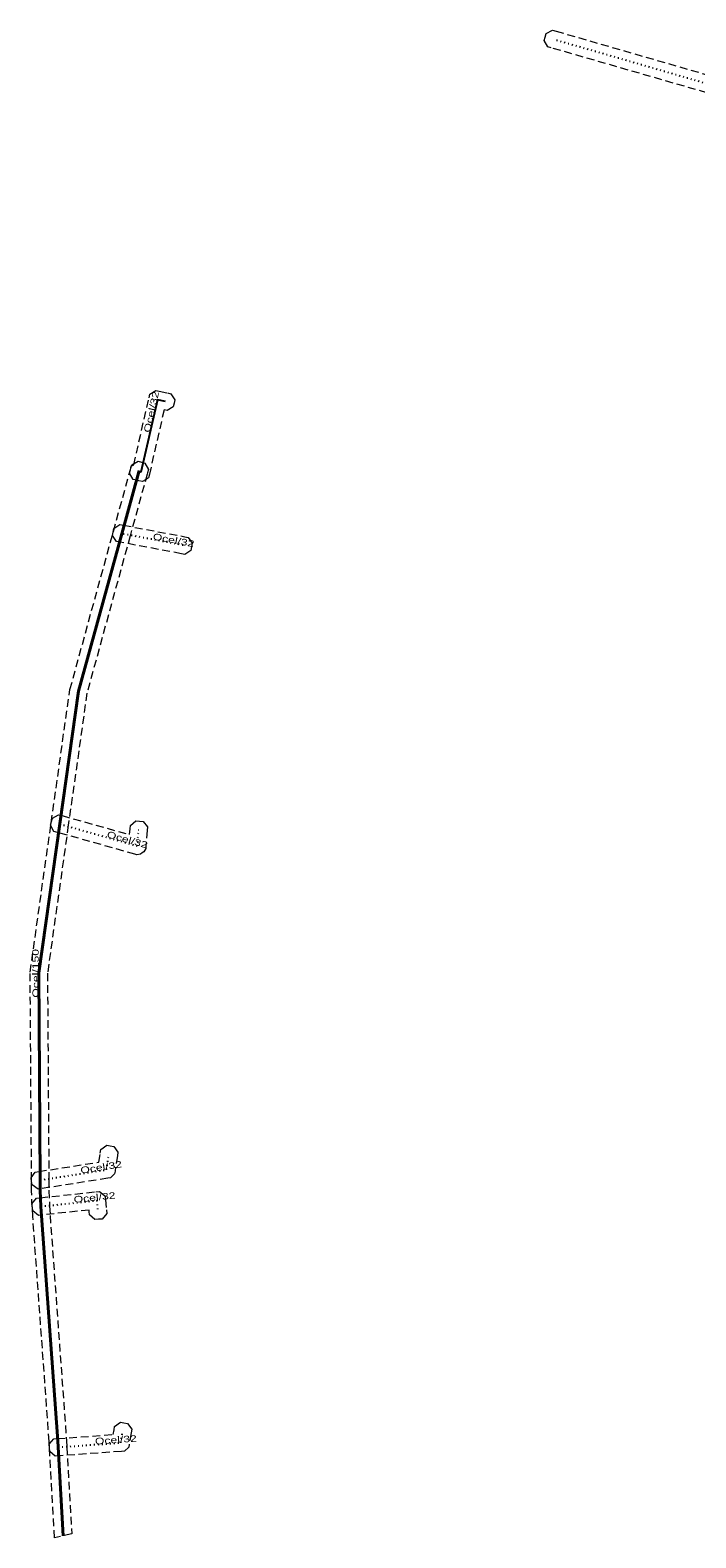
# Model space of a CAD drawing. Extents: x -583333 to -583115, y -1209681 to -1209498.
# Drawn here: x -583332.7 to -583255.9, y -1209681.3 to -1209507.4 of the extents above; entities that cross this region are included whole.
import ezdxf

# ---------------------------------------------------------------- set-up
doc = ezdxf.new("R2010")
doc.units = 0
doc.header["$LTSCALE"] = 0.3
doc.linetypes.add('DOTTED', pattern=[1.5, 0.3, -1.2])
doc.linetypes.add('MEDIUM_DASHED', pattern=[4.5, 3, -1.5])
for name, color, linetype, lineweight in [('1', 7, 'MEDIUM_DASHED', 13), ('14', 7, 'Continuous', 40), ('18', 7, 'DOTTED', 25)]:
    doc.layers.add(name, color=color, linetype=linetype, lineweight=lineweight)
doc.layers.add('20', color=7, linetype='Continuous')

msp = doc.modelspace()

# ---------------------------------------------------------------- linework, layer by layer
at = {"layer": '1'}
for points in [[(-583232.408, -1209539.651), (-583232.555, -1209539.264), (-583240.332, -1209518.712), (-583272.551, -1209509.395), (-583272.949, -1209509.28), (-583273.349, -1209508.554), (-583273.234, -1209508.156), (-583273.119, -1209507.758), (-583272.393, -1209507.358), (-583271.995, -1209507.473), (-583239.296, -1209516.929), (-583239.069, -1209516.995), (-583238.723, -1209517.315), (-583238.639, -1209517.536), (-583230.685, -1209538.556), (-583230.538, -1209538.943), (-583230.879, -1209539.698), (-583231.266, -1209539.845), (-583231.653, -1209539.992)], [(-583321.005, -1209557.674), (-583320.705, -1209557.49), (-583318.945, -1209549.768), (-583318.854, -1209549.368), (-583318.161, -1209548.926), (-583317.76, -1209549.012), (-583316.83, -1209549.212), (-583316.425, -1209549.299), (-583315.975, -1209549.995), (-583316.062, -1209550.4), (-583316.149, -1209550.805), (-583316.845, -1209551.255), (-583317.215, -1209551.176), (-583318.905, -1209558.592), (-583318.998, -1209558.999), (-583319.353, -1209559.22), (-583319.707, -1209559.44), (-583320.113, -1209559.342), (-583320.363, -1209559.282), (-583320.766, -1209559.185), (-583321.199, -1209558.48), (-583321.102, -1209558.077)], [(-583327.861, -1209680.815), (-583329.837, -1209681.295), (-583330.428, -1209670.896), (-583330.468, -1209670.174), (-583332.358, -1209644.209), (-583332.409, -1209643.107), (-583332.5, -1209641.244), (-583332.5, -1209640.023), (-583332.66, -1209616.033), (-583330.24, -1209598.801), (-583328.071, -1209583.427), (-583323.054, -1209565.185), (-583321.093, -1209558.04), (-583321.052, -1209557.895), (-583320.938, -1209557.497), (-583320.213, -1209557.095), (-583319.815, -1209557.208), (-583319.417, -1209557.322), (-583319.015, -1209558.047), (-583319.128, -1209558.445), (-583319.167, -1209558.58), (-583321.126, -1209565.715), (-583326.109, -1209583.833), (-583328.26, -1209599.079), (-583330.66, -1209616.167), (-583330.5, -1209640.017), (-583330.5, -1209641.196), (-583330.411, -1209643.013), (-583330.362, -1209644.091), (-583328.472, -1209670.046), (-583328.432, -1209670.784)], [(-583314.798, -1209567.84), (-583315.205, -1209567.763), (-583322.275, -1209566.433), (-583322.682, -1209566.356), (-583323.15, -1209565.672), (-583323.073, -1209565.265), (-583322.996, -1209564.858), (-583322.312, -1209564.39), (-583321.905, -1209564.467), (-583314.835, -1209565.797), (-583314.428, -1209565.874), (-583313.96, -1209566.558), (-583314.037, -1209566.965), (-583314.114, -1209567.372)], [(-583329.378, -1209597.865), (-583328.979, -1209597.977), (-583321.193, -1209600.17), (-583321.136, -1209599.514), (-583321.101, -1209599.101), (-583320.467, -1209598.568), (-583320.054, -1209598.604), (-583319.641, -1209598.639), (-583319.108, -1209599.273), (-583319.144, -1209599.686), (-583319.304, -1209601.546), (-583319.323, -1209601.769), (-583319.547, -1209602.155), (-583319.731, -1209602.282), (-583319.915, -1209602.409), (-583320.356, -1209602.483), (-583320.571, -1209602.423), (-583329.521, -1209599.903), (-583329.92, -1209599.791), (-583330.325, -1209599.068), (-583330.213, -1209598.669), (-583330.101, -1209598.27)], [(-583332.064, -1209639.096), (-583331.655, -1209639.032), (-583324.733, -1209637.945), (-583324.568, -1209636.903), (-583324.503, -1209636.494), (-583323.832, -1209636.007), (-583323.423, -1209636.072), (-583323.014, -1209636.137), (-583322.527, -1209636.808), (-583322.592, -1209637.217), (-583322.872, -1209638.977), (-583322.923, -1209639.298), (-583323.384, -1209639.757), (-583323.705, -1209639.808), (-583331.345, -1209641.008), (-583331.754, -1209641.072), (-583332.424, -1209640.584), (-583332.488, -1209640.175), (-583332.552, -1209639.766)], [(-583331.928, -1209642.11), (-583331.516, -1209642.066), (-583325.066, -1209641.376), (-583324.648, -1209641.331), (-583324.324, -1209641.599), (-583323.999, -1209641.866), (-583323.964, -1209642.286), (-583323.864, -1209643.466), (-583323.829, -1209643.879), (-583324.363, -1209644.511), (-583324.776, -1209644.546), (-583325.189, -1209644.581), (-583325.821, -1209644.047), (-583325.856, -1209643.634), (-583325.87, -1209643.473), (-583331.304, -1209644.054), (-583331.716, -1209644.098), (-583332.36, -1209643.578), (-583332.404, -1209643.166), (-583332.448, -1209642.754)], [(-583329.915, -1209669.872), (-583329.502, -1209669.843), (-583323.072, -1209669.379), (-583322.987, -1209668.852), (-583322.922, -1209668.443), (-583322.251, -1209667.957), (-583321.842, -1209668.023), (-583321.433, -1209668.088), (-583320.947, -1209668.759), (-583321.013, -1209669.168), (-583321.223, -1209670.478), (-583321.278, -1209670.822), (-583321.791, -1209671.292), (-583322.138, -1209671.317), (-583329.358, -1209671.837), (-583329.771, -1209671.867), (-583330.398, -1209671.325), (-583330.427, -1209670.912), (-583330.457, -1209670.499)]]:
    msp.add_lwpolyline(points, close=True, dxfattribs=at)
at = {"layer": '14', "lineweight": 25}
msp.add_lwpolyline([(-583317.04, -1209550.19), (-583317.97, -1209549.99), (-583319.88, -1209558.37), (-583320.13, -1209558.31)], dxfattribs=at)
at = {"layer": '14'}
msp.add_lwpolyline([(-583328.849, -1209681.055), (-583329.43, -1209670.84), (-583329.47, -1209670.11), (-583331.36, -1209644.15), (-583331.41, -1209643.06), (-583331.5, -1209641.22), (-583331.5, -1209640.02), (-583331.66, -1209616.1), (-583329.25, -1209598.94), (-583327.09, -1209583.63), (-583322.09, -1209565.45), (-583320.13, -1209558.31), (-583320.09, -1209558.17)], dxfattribs=at)
at = {"layer": '18'}
msp.add_line((-583315.02, -1209566.78), (-583322.09, -1209565.45), dxfattribs=at)
for points in [[(-583231.62, -1209538.91), (-583239.574, -1209517.89), (-583272.273, -1209508.434)], [(-583329.25, -1209598.94), (-583320.3, -1209601.46), (-583320.14, -1209599.6)], [(-583331.5, -1209640.02), (-583323.86, -1209638.82), (-583323.58, -1209637.06)], [(-583331.41, -1209643.06), (-583324.96, -1209642.37), (-583324.86, -1209643.55)], [(-583329.43, -1209670.84), (-583322.21, -1209670.32), (-583322, -1209669.01)]]:
    msp.add_lwpolyline(points, dxfattribs=at)

# ---------------------------------------------------------------- texts
at = {"layer": '20', "width": 1.4}
for s, rotation, p in [('Ocel/32', 77.16, (-583318.848, -1209553.841)), ('Ocel/32', 349.346, (-583318.555, -1209566.115)), ('Ocel/32', 344.275, (-583323.876, -1209600.453)), ('Ocel/150', 90.383, (-583331.641, -1209618.976)), ('Ocel/32', 8.926, (-583326.8, -1209639.282)), ('Ocel/32', 6.106, (-583327.596, -1209642.652)), ('Ocel/32', 4.119, (-583325.159, -1209670.532))]:
    msp.add_text(s, height=0.75, rotation=rotation, dxfattribs=at).set_placement(p)

doc.saveas('drawing.dxf')
